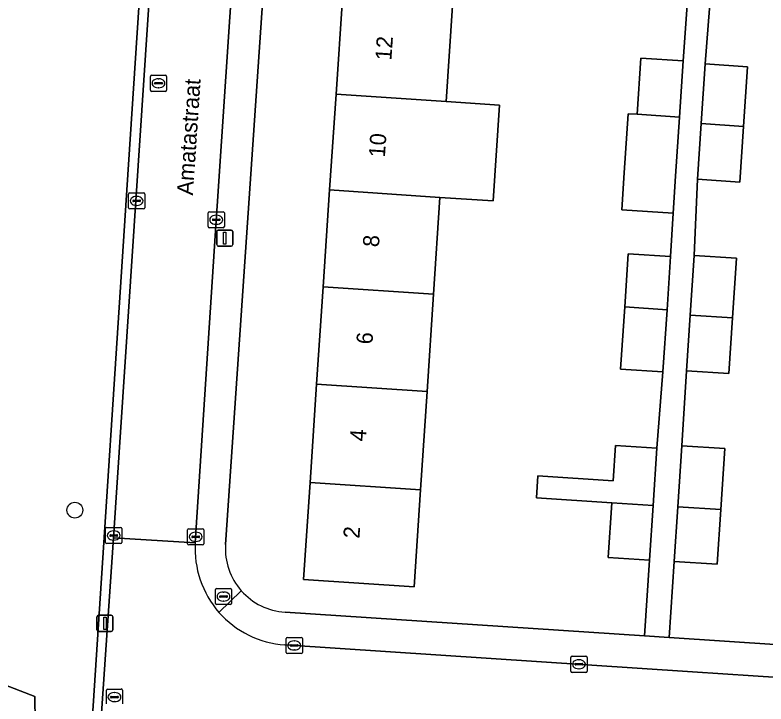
# Model space of a CAD drawing. Extents: x 161848 to 162726, y 385382 to 386521.
# Drawn here: x 161938.67 to 161985.14, y 385769.85 to 385812.47 of the extents above; entities that cross this region are included whole.
import ezdxf

# ---------------------------------------------------------------- set-up
doc = ezdxf.new("R2010")
doc.units = 0
for name, color, linetype in [('IMGEO_Berm_groen', 7, 'Continuous'), ('IMGEO_Boom', 7, 'Continuous'), ('IMGEO_Brandkraan', 7, 'Continuous'), ('IMGEO_Erf', 7, 'Continuous'), ('IMGEO_Kolk', 7, 'Continuous'), ('IMGEO_Lichtmast', 7, 'Continuous'), ('IMGEO_Openbare_ruimte_label', 7, 'Continuous'), ('IMGEO_Pand', 7, 'Continuous'), ('IMGEO_Pand_nummerreeks', 7, 'Continuous'), ('IMGEO_Rijbaan_lokaal_open', 7, 'Continuous'), ('IMGEO_Rioolput', 7, 'Continuous'), ('IMGEO_Verkeerseiland_open', 7, 'Continuous'), ('IMGEO_Voetpad_open', 7, 'Continuous')]:
    doc.layers.add(name, color=color, linetype=linetype)

msp = doc.modelspace()

# ---------------------------------------------------------------- linework, layer by layer
at = {"layer": 'IMGEO_Berm_groen'}
msp.add_lwpolyline([(161931.525, 385832.871), (161933.818, 385847.74), (161934.084, 385852.209), (161933.585, 385852.239), (161932.486, 385852.287), (161932.221, 385847.839), (161924.449, 385848.323), (161920.862, 385793.562), (161908.293, 385794.092), (161907.152, 385778.61), (161908.997, 385778.473), (161908.591, 385768.327), (161908.991, 385768.299), (161939.908, 385768.742), (161939.891, 385770.318), (161927.656, 385775.034)], close=True, dxfattribs=at)
msp.add_lwpolyline([(161947.7, 385838.093), (161943.41, 385838.314), (161943.973, 385847.108), (161933.818, 385847.74), (161931.525, 385832.871), (161927.656, 385775.034), (161939.891, 385770.318), (161939.908, 385768.742), (161943.443, 385768.793), (161945.684, 385803.221), (161947.829, 385835.828)], dxfattribs=at)
at = {"layer": 'IMGEO_Boom'}
msp.add_circle((161942.377, 385781.84), 0.489, dxfattribs=at)
at = {"layer": 'IMGEO_Brandkraan'}
for p, q in [((161951.072, 385776.073), (161951.072, 385776.925)), ((161951.147, 385776.999), (161951.999, 385776.999)), ((161951.56, 385776.779), (161951.585, 385776.779)), ((161952.073, 385776.925), (161952.073, 385776.073)), ((161951.331, 385776.493), (161951.331, 385776.505)), ((161951.769, 385776.456), (161951.371, 385776.456)), ((161951.374, 385776.542), (161951.772, 385776.542)), ((161951.583, 385776.219), (161951.558, 385776.219)), ((161951.815, 385776.505), (161951.815, 385776.493)), ((161951.999, 385775.999), (161951.147, 385775.999))]:
    msp.add_line(p, q, dxfattribs=at)
for points in [[(161951.072, 385776.073), (161951.072, 385776.925)], [(161951.147, 385776.999), (161951.999, 385776.999)], [(161952.073, 385776.925), (161952.073, 385776.073)], [(161951.999, 385775.999), (161951.147, 385775.999)]]:
    msp.add_lwpolyline(points, dxfattribs=at)
for centre, radius, start, end in [((161951.149, 385776.923), 0.0765, 91.552, 178.448), ((161951.149, 385776.923), 0.0765, 91.552, 178.448), ((161951.997, 385776.923), 0.0765, 1.552, 88.448), ((161951.997, 385776.923), 0.0765, 1.552, 88.448), ((161951.371, 385776.502), 0.0403, 85.8775, 175.7526), ((161951.368, 385776.492), 0.0366, 178.938, 274.7102), ((161951.772, 385776.499), 0.043, 264.8664, 352.4533), ((161951.776, 385776.504), 0.0386, 1.7309, 96.639), ((161951.149, 385776.075), 0.0765, 181.552, 268.448), ((161951.149, 385776.075), 0.0765, 181.552, 268.448), ((161951.997, 385776.075), 0.0765, 271.552, 358.448), ((161951.997, 385776.075), 0.0765, 271.552, 358.448)]:
    msp.add_arc(centre, radius, start, end, dxfattribs=at)
for centre, major_axis, ratio, start_param, end_param in [((161951.559, 385776.499), (-0.387, 0.002), 0.722429, 4.712389, 7.853982), ((161951.584, 385776.499), (-0.39, 0.002), 0.717154, 1.570796, 4.712389)]:
    msp.add_ellipse(centre, major_axis=major_axis, ratio=ratio, start_param=start_param, end_param=end_param, dxfattribs=at)
at = {"layer": 'IMGEO_Erf'}
for points in [[(161977.392, 385809.804), (161980.014, 385809.631), (161980.348, 385814.258), (161977.727, 385814.432), (161977.978, 385818.234), (161978.199, 385821.56), (161980.821, 385821.387), (161981.18, 385826.49), (161978.559, 385826.664), (161978.792, 385830.19), (161979.031, 385833.792), (161981.653, 385833.619), (161982.073, 385839.965), (161959.679, 385841.448)], [(161955.683, 385837.954), (161951.696, 385779.71)], [(161981.747, 385814.218), (161981.378, 385809.448), (161983.998, 385809.274), (161983.753, 385805.579), (161983.525, 385802.138), (161980.905, 385802.312), (161980.693, 385797.6), (161983.313, 385797.426), (161983.069, 385793.741), (161982.84, 385790.29), (161980.22, 385790.464), (161979.94, 385785.823), (161982.587, 385785.648), (161982.339, 385781.883), (161982.116, 385778.499), (161979.469, 385778.674), (161979.158, 385773.957), (162000, 385772.581), (162004.679, 385772.273)], [(161965.751, 385813.03), (161965.359, 385807.121), (161968.654, 385806.9), (161968.257, 385800.972), (161964.966, 385801.192), (161964.57, 385795.208), (161964.17, 385789.179), (161963.767, 385783.092), (161963.37, 385777.097), (161956.525, 385777.555), (161956.926, 385783.55), (161957.334, 385789.637), (161957.737, 385795.665), (161958.138, 385801.649), (161958.535, 385807.578), (161958.93, 385813.487)], [(161955.379, 385775.527), (161977.618, 385774.059), (161977.928, 385778.75), (161975.378, 385778.918), (161975.601, 385782.3), (161970.933, 385782.613), (161971.023, 385783.969), (161975.691, 385783.656), (161975.835, 385785.839), (161978.385, 385785.671), (161978.764, 385790.4), (161976.143, 385790.574), (161976.397, 385794.417), (161976.615, 385797.702), (161979.237, 385797.529), (161979.389, 385800.205), (161976.217, 385800.415), (161976.369, 385802.713), (161976.612, 385806.368), (161977.162, 385806.331), (161977.392, 385809.804)]]:
    msp.add_lwpolyline(points, dxfattribs=at)
for centre, radius, start, end in [((161955.636, 385779.468), 3.948, 176.479, 221.3765), ((161955.638, 385779.468), 3.949, 221.3634, 266.2374)]:
    msp.add_arc(centre, radius, start, end, dxfattribs=at)
at = {"layer": 'IMGEO_Kolk'}
for p, q in [((161945.699, 385800.546), (161945.699, 385801.398)), ((161945.774, 385801.472), (161946.626, 385801.472)), ((161946.7, 385801.398), (161946.7, 385800.546)), ((161945.958, 385800.966), (161945.958, 385800.978)), ((161946.396, 385800.929), (161945.998, 385800.929)), ((161946.001, 385801.015), (161946.399, 385801.015)), ((161946.187, 385801.252), (161946.212, 385801.252)), ((161946.442, 385800.978), (161946.442, 385800.966)), ((161946.626, 385800.472), (161945.774, 385800.472)), ((161946.21, 385800.692), (161946.185, 385800.692)), ((161950.623, 385799.379), (161950.623, 385800.231)), ((161950.698, 385800.305), (161951.55, 385800.305)), ((161951.111, 385800.085), (161951.136, 385800.085)), ((161951.624, 385800.231), (161951.624, 385799.379)), ((161950.882, 385799.799), (161950.882, 385799.811)), ((161951.32, 385799.762), (161950.922, 385799.762)), ((161950.925, 385799.848), (161951.323, 385799.848)), ((161951.134, 385799.525), (161951.109, 385799.525)), ((161951.366, 385799.811), (161951.366, 385799.799)), ((161951.55, 385799.305), (161950.698, 385799.305)), ((161944.277, 385779.848), (161944.277, 385780.7)), ((161944.352, 385780.774), (161945.204, 385780.774)), ((161944.765, 385780.554), (161944.79, 385780.554)), ((161945.278, 385780.7), (161945.278, 385779.848)), ((161949.351, 385779.766), (161949.351, 385780.618)), ((161949.426, 385780.692), (161950.278, 385780.692)), ((161949.839, 385780.472), (161949.864, 385780.472)), ((161950.352, 385780.618), (161950.352, 385779.766)), ((161944.536, 385780.268), (161944.536, 385780.28)), ((161944.974, 385780.231), (161944.576, 385780.231)), ((161944.579, 385780.317), (161944.977, 385780.317)), ((161944.788, 385779.994), (161944.763, 385779.994)), ((161945.02, 385780.28), (161945.02, 385780.268)), ((161949.61, 385780.186), (161949.61, 385780.198)), ((161950.048, 385780.149), (161949.65, 385780.149)), ((161949.653, 385780.235), (161950.051, 385780.235)), ((161949.862, 385779.912), (161949.837, 385779.912)), ((161950.094, 385780.198), (161950.094, 385780.186)), ((161945.204, 385779.774), (161944.352, 385779.774)), ((161950.278, 385779.692), (161949.426, 385779.692)), ((161955.451, 385773.048), (161955.451, 385773.9)), ((161955.526, 385773.974), (161956.378, 385773.974)), ((161956.452, 385773.9), (161956.452, 385773.048)), ((161955.71, 385773.468), (161955.71, 385773.48)), ((161956.148, 385773.431), (161955.75, 385773.431)), ((161955.753, 385773.517), (161956.151, 385773.517)), ((161955.939, 385773.754), (161955.964, 385773.754)), ((161956.194, 385773.48), (161956.194, 385773.468)), ((161956.378, 385772.974), (161955.526, 385772.974)), ((161955.962, 385773.194), (161955.937, 385773.194)), ((161973.067, 385771.883), (161973.067, 385772.735)), ((161973.142, 385772.809), (161973.994, 385772.809)), ((161973.555, 385772.589), (161973.58, 385772.589)), ((161974.068, 385772.735), (161974.068, 385771.883)), ((161973.326, 385772.303), (161973.326, 385772.315)), ((161973.764, 385772.266), (161973.366, 385772.266)), ((161973.369, 385772.352), (161973.767, 385772.352)), ((161973.578, 385772.029), (161973.553, 385772.029)), ((161973.81, 385772.315), (161973.81, 385772.303)), ((161973.994, 385771.809), (161973.142, 385771.809))]:
    msp.add_line(p, q, dxfattribs=at)
for points in [[(161945.699, 385800.546), (161945.699, 385801.398)], [(161945.774, 385801.472), (161946.626, 385801.472)], [(161946.7, 385801.398), (161946.7, 385800.546)], [(161946.626, 385800.472), (161945.774, 385800.472)], [(161950.623, 385799.379), (161950.623, 385800.231)], [(161950.698, 385800.305), (161951.55, 385800.305)], [(161951.624, 385800.231), (161951.624, 385799.379)], [(161951.55, 385799.305), (161950.698, 385799.305)], [(161944.277, 385779.848), (161944.277, 385780.7)], [(161944.352, 385780.774), (161945.204, 385780.774)], [(161945.278, 385780.7), (161945.278, 385779.848)], [(161949.351, 385779.766), (161949.351, 385780.618)], [(161949.426, 385780.692), (161950.278, 385780.692)], [(161950.352, 385780.618), (161950.352, 385779.766)], [(161945.204, 385779.774), (161944.352, 385779.774)], [(161950.278, 385779.692), (161949.426, 385779.692)], [(161955.451, 385773.048), (161955.451, 385773.9)], [(161955.526, 385773.974), (161956.378, 385773.974)], [(161956.452, 385773.9), (161956.452, 385773.048)], [(161956.378, 385772.974), (161955.526, 385772.974)], [(161973.067, 385771.883), (161973.067, 385772.735)], [(161973.142, 385772.809), (161973.994, 385772.809)], [(161974.068, 385772.735), (161974.068, 385771.883)], [(161973.994, 385771.809), (161973.142, 385771.809)]]:
    msp.add_lwpolyline(points, dxfattribs=at)
for centre, radius, start, end in [((161945.776, 385801.396), 0.0765, 91.552, 178.448), ((161945.776, 385801.396), 0.0765, 91.552, 178.448), ((161946.624, 385801.396), 0.0765, 1.552, 88.448), ((161946.624, 385801.396), 0.0765, 1.552, 88.448), ((161945.998, 385800.975), 0.0403, 85.8775, 175.7526), ((161945.995, 385800.965), 0.0366, 178.938, 274.7102), ((161946.399, 385800.972), 0.043, 264.8664, 352.4533), ((161946.403, 385800.977), 0.0386, 1.7309, 96.639), ((161945.776, 385800.548), 0.0765, 181.552, 268.448), ((161945.776, 385800.548), 0.0765, 181.552, 268.448), ((161946.624, 385800.548), 0.0765, 271.552, 358.448), ((161946.624, 385800.548), 0.0765, 271.552, 358.448), ((161950.7, 385800.229), 0.0765, 91.552, 178.448), ((161950.7, 385800.229), 0.0765, 91.552, 178.448), ((161951.548, 385800.229), 0.0765, 1.552, 88.448), ((161951.548, 385800.229), 0.0765, 1.552, 88.448), ((161950.922, 385799.808), 0.0403, 85.8775, 175.7526), ((161950.919, 385799.798), 0.0366, 178.938, 274.7102), ((161951.323, 385799.805), 0.043, 264.8664, 352.4533), ((161951.327, 385799.81), 0.0386, 1.7309, 96.639), ((161950.7, 385799.381), 0.0765, 181.552, 268.448), ((161950.7, 385799.381), 0.0765, 181.552, 268.448), ((161951.548, 385799.381), 0.0765, 271.552, 358.448), ((161951.548, 385799.381), 0.0765, 271.552, 358.448), ((161944.354, 385780.698), 0.0765, 91.552, 178.448), ((161944.354, 385780.698), 0.0765, 91.552, 178.448), ((161945.202, 385780.698), 0.0765, 1.552, 88.448), ((161945.202, 385780.698), 0.0765, 1.552, 88.448), ((161949.428, 385780.616), 0.0765, 91.552, 178.448), ((161949.428, 385780.616), 0.0765, 91.552, 178.448), ((161950.276, 385780.616), 0.0765, 1.552, 88.448), ((161950.276, 385780.616), 0.0765, 1.552, 88.448), ((161944.576, 385780.277), 0.0403, 85.8775, 175.7526), ((161944.573, 385780.267), 0.0366, 178.938, 274.7102), ((161944.977, 385780.274), 0.043, 264.8664, 352.4533), ((161944.981, 385780.279), 0.0386, 1.7309, 96.639), ((161949.65, 385780.195), 0.0403, 85.8775, 175.7526), ((161949.647, 385780.185), 0.0366, 178.938, 274.7102), ((161950.051, 385780.192), 0.043, 264.8664, 352.4533), ((161950.055, 385780.197), 0.0386, 1.7309, 96.639), ((161944.354, 385779.85), 0.0765, 181.552, 268.448), ((161944.354, 385779.85), 0.0765, 181.552, 268.448), ((161945.202, 385779.85), 0.0765, 271.552, 358.448), ((161945.202, 385779.85), 0.0765, 271.552, 358.448), ((161949.428, 385779.768), 0.0765, 181.552, 268.448), ((161949.428, 385779.768), 0.0765, 181.552, 268.448), ((161950.276, 385779.768), 0.0765, 271.552, 358.448), ((161950.276, 385779.768), 0.0765, 271.552, 358.448), ((161955.528, 385773.898), 0.0765, 91.552, 178.448), ((161955.528, 385773.898), 0.0765, 91.552, 178.448), ((161956.376, 385773.898), 0.0765, 1.552, 88.448), ((161956.376, 385773.898), 0.0765, 1.552, 88.448), ((161955.75, 385773.477), 0.0403, 85.8775, 175.7526), ((161955.747, 385773.467), 0.0366, 178.938, 274.7102), ((161956.151, 385773.474), 0.043, 264.8664, 352.4533), ((161956.155, 385773.479), 0.0386, 1.7309, 96.639), ((161955.528, 385773.05), 0.0765, 181.552, 268.448), ((161955.528, 385773.05), 0.0765, 181.552, 268.448), ((161956.376, 385773.05), 0.0765, 271.552, 358.448), ((161956.376, 385773.05), 0.0765, 271.552, 358.448), ((161973.144, 385772.733), 0.0765, 91.552, 178.448), ((161973.144, 385772.733), 0.0765, 91.552, 178.448), ((161973.992, 385772.733), 0.0765, 1.552, 88.448), ((161973.992, 385772.733), 0.0765, 1.552, 88.448), ((161973.366, 385772.312), 0.0403, 85.8775, 175.7526), ((161973.363, 385772.302), 0.0366, 178.938, 274.7102), ((161973.767, 385772.309), 0.043, 264.8664, 352.4533), ((161973.771, 385772.314), 0.0386, 1.7309, 96.639), ((161973.144, 385771.885), 0.0765, 181.552, 268.448), ((161973.144, 385771.885), 0.0765, 181.552, 268.448), ((161973.992, 385771.885), 0.0765, 271.552, 358.448), ((161973.992, 385771.885), 0.0765, 271.552, 358.448)]:
    msp.add_arc(centre, radius, start, end, dxfattribs=at)
for centre, major_axis, ratio, start_param, end_param in [((161946.186, 385800.972), (-0.387, 0.002), 0.722429, 4.712389, 7.853982), ((161946.211, 385800.972), (-0.39, 0.002), 0.717154, 1.570796, 4.712389), ((161951.11, 385799.805), (-0.387, 0.002), 0.722429, 4.712389, 7.853982), ((161951.135, 385799.805), (-0.39, 0.002), 0.717154, 1.570796, 4.712389), ((161944.764, 385780.274), (-0.387, 0.002), 0.722429, 4.712389, 7.853982), ((161944.789, 385780.274), (-0.39, 0.002), 0.717154, 1.570796, 4.712389), ((161949.838, 385780.192), (-0.387, 0.002), 0.722429, 4.712389, 7.853982), ((161949.863, 385780.192), (-0.39, 0.002), 0.717154, 1.570796, 4.712389), ((161955.938, 385773.474), (-0.387, 0.002), 0.722429, 4.712389, 7.853982), ((161955.963, 385773.474), (-0.39, 0.002), 0.717154, 1.570796, 4.712389), ((161973.554, 385772.309), (-0.387, 0.002), 0.722429, 4.712389, 7.853982), ((161973.579, 385772.309), (-0.39, 0.002), 0.717154, 1.570796, 4.712389)]:
    msp.add_ellipse(centre, major_axis=major_axis, ratio=ratio, start_param=start_param, end_param=end_param, dxfattribs=at)
at = {"layer": 'IMGEO_Lichtmast'}
for p, q in [((161951.15, 385798.271), (161951.15, 385799.071)), ((161951.15, 385799.071), (161951.15, 385798.271)), ((161951.25, 385799.171), (161952.04, 385799.171)), ((161952.04, 385799.171), (161951.25, 385799.171)), ((161952.14, 385799.071), (161952.14, 385798.271)), ((161952.14, 385798.271), (161952.14, 385799.071)), ((161952.04, 385798.171), (161951.25, 385798.171)), ((161951.25, 385798.171), (161952.04, 385798.171)), ((161943.74, 385774.443), (161943.74, 385775.243)), ((161943.74, 385775.243), (161943.74, 385774.443)), ((161943.84, 385775.343), (161944.63, 385775.343)), ((161944.63, 385775.343), (161943.84, 385775.343)), ((161944.73, 385775.243), (161944.73, 385774.443)), ((161944.73, 385774.443), (161944.73, 385775.243)), ((161944.63, 385774.343), (161943.84, 385774.343)), ((161943.84, 385774.343), (161944.63, 385774.343))]:
    msp.add_line(p, q, dxfattribs=at)
for points in [[(161951.57, 385799.046), (161951.72, 385799.046), (161951.72, 385798.296), (161951.57, 385798.296), (161951.57, 385799.046)], [(161944.16, 385775.218), (161944.31, 385775.218), (161944.31, 385774.468), (161944.16, 385774.468), (161944.16, 385775.218)]]:
    msp.add_lwpolyline(points, dxfattribs=at)
for centre, start, end in [((161951.25, 385799.071), 90, 180), ((161951.25, 385799.071), 90, 180), ((161952.04, 385799.071), 0, 90), ((161952.04, 385799.071), 360, 90), ((161951.25, 385798.271), 180, 270), ((161951.25, 385798.271), 180, 270), ((161952.04, 385798.271), 270, 0), ((161952.04, 385798.271), 270, 0), ((161943.84, 385775.243), 90, 180), ((161943.84, 385775.243), 90, 180), ((161944.63, 385775.243), 0, 90), ((161944.63, 385775.243), 360, 90), ((161943.84, 385774.443), 180, 270), ((161943.84, 385774.443), 180, 270), ((161944.63, 385774.443), 270, 0), ((161944.63, 385774.443), 270, 0)]:
    msp.add_arc(centre, 0.1, start, end, dxfattribs=at)
at = {"layer": 'IMGEO_Pand'}
for points in [[(161965.359, 385807.121), (161965.751, 385813.03), (161958.93, 385813.487), (161958.535, 385807.578)], [(161980.014, 385809.631), (161977.392, 385809.804), (161977.162, 385806.331), (161979.783, 385806.155)], [(161983.998, 385809.274), (161981.378, 385809.448), (161981.133, 385805.752), (161983.753, 385805.579)], [(161968.654, 385806.9), (161965.359, 385807.121), (161958.535, 385807.578), (161958.138, 385801.649), (161964.966, 385801.192), (161968.257, 385800.972)], [(161979.783, 385806.155), (161977.162, 385806.331), (161976.612, 385806.368), (161976.369, 385802.713), (161976.217, 385800.415), (161979.389, 385800.205), (161979.541, 385802.502)], [(161980.905, 385802.312), (161983.525, 385802.138), (161983.753, 385805.579), (161981.133, 385805.752)], [(161958.138, 385801.649), (161957.737, 385795.665), (161964.57, 385795.208), (161964.966, 385801.192)], [(161979.237, 385797.529), (161976.615, 385797.702), (161976.397, 385794.417), (161979.019, 385794.242)], [(161983.313, 385797.426), (161980.693, 385797.6), (161980.449, 385793.914), (161983.069, 385793.741)], [(161964.17, 385789.179), (161964.57, 385795.208), (161957.737, 385795.665), (161957.334, 385789.637)], [(161976.143, 385790.574), (161978.764, 385790.4), (161979.019, 385794.242), (161976.397, 385794.417)], [(161980.22, 385790.464), (161982.84, 385790.29), (161983.069, 385793.741), (161980.449, 385793.914)], [(161963.767, 385783.092), (161964.17, 385789.179), (161957.334, 385789.637), (161956.926, 385783.55)], [(161978.385, 385785.671), (161975.835, 385785.839), (161975.691, 385783.656), (161971.023, 385783.969), (161970.933, 385782.613), (161975.601, 385782.3), (161978.151, 385782.129)], [(161982.339, 385781.883), (161982.587, 385785.648), (161979.94, 385785.823), (161979.692, 385782.058)], [(161956.926, 385783.55), (161956.525, 385777.555), (161963.37, 385777.097), (161963.767, 385783.092)], [(161975.601, 385782.3), (161975.378, 385778.918), (161977.928, 385778.75), (161978.151, 385782.129)], [(161979.692, 385782.058), (161979.469, 385778.674), (161982.116, 385778.499), (161982.339, 385781.883)]]:
    msp.add_lwpolyline(points, close=True, dxfattribs=at)
at = {"layer": 'IMGEO_Rijbaan_lokaal_open'}
msp.add_lwpolyline([(161953.684, 385837.905), (161948.626, 385838.255), (161948.566, 385837.444), (161948.494, 385836.471), (161944.769, 385780.141), (161949.827, 385779.824), (161951.056, 385798.814)], close=True, dxfattribs=at)
for points in [[(161949.827, 385779.824), (161944.769, 385780.141), (161944.03, 385769.276), (162000, 385765.501), (162001.676, 385765.394), (162004.668, 385765.161), (162006.857, 385764.99), (162007.207, 385770.068), (162005.411, 385770.176), (162000, 385770.558), (161984.346, 385771.594)], [(161984.346, 385771.594), (161980.601, 385771.842), (161955.369, 385773.511)]]:
    msp.add_lwpolyline(points, dxfattribs=at)
for centre, radius, start, end in [((161955.76, 385779.443), 5.945, 176.326, 221.2774), ((161955.76, 385779.445), 5.946, 221.286, 266.2265)]:
    msp.add_arc(centre, radius, start, end, dxfattribs=at)
at = {"layer": 'IMGEO_Rioolput'}
for p, q in [((161947.125, 385808.748), (161947.977, 385808.748)), ((161947.05, 385807.822), (161947.05, 385808.674)), ((161947.309, 385808.242), (161947.309, 385808.254)), ((161947.352, 385808.291), (161947.75, 385808.291)), ((161947.538, 385808.528), (161947.563, 385808.528)), ((161947.793, 385808.254), (161947.793, 385808.242)), ((161948.051, 385808.674), (161948.051, 385807.822)), ((161947.747, 385808.205), (161947.349, 385808.205)), ((161947.561, 385807.968), (161947.536, 385807.968)), ((161947.977, 385807.748), (161947.125, 385807.748)), ((161944.322, 385769.854), (161944.322, 385770.706)), ((161944.397, 385770.78), (161945.249, 385770.78)), ((161945.323, 385770.706), (161945.323, 385769.854)), ((161944.581, 385770.274), (161944.581, 385770.286)), ((161945.019, 385770.237), (161944.621, 385770.237)), ((161944.624, 385770.323), (161945.022, 385770.323)), ((161944.81, 385770.56), (161944.835, 385770.56)), ((161945.065, 385770.286), (161945.065, 385770.274)), ((161944.833, 385770), (161944.808, 385770))]:
    msp.add_line(p, q, dxfattribs=at)
for points in [[(161947.125, 385808.748), (161947.977, 385808.748)], [(161947.05, 385807.822), (161947.05, 385808.674)], [(161948.051, 385808.674), (161948.051, 385807.822)], [(161947.977, 385807.748), (161947.125, 385807.748)], [(161944.322, 385769.854), (161944.322, 385770.706)], [(161944.397, 385770.78), (161945.249, 385770.78)], [(161945.323, 385770.706), (161945.323, 385769.854)]]:
    msp.add_lwpolyline(points, dxfattribs=at)
for centre, radius, start, end in [((161947.127, 385808.672), 0.0765, 91.552, 178.448), ((161947.127, 385808.672), 0.0765, 91.552, 178.448), ((161947.975, 385808.672), 0.0765, 1.552, 88.448), ((161947.975, 385808.672), 0.0765, 1.552, 88.448), ((161947.349, 385808.251), 0.0403, 85.8775, 175.7526), ((161947.346, 385808.241), 0.0366, 178.938, 274.7102), ((161947.75, 385808.248), 0.043, 264.8664, 352.4533), ((161947.754, 385808.253), 0.0386, 1.7309, 96.639), ((161947.127, 385807.824), 0.0765, 181.552, 268.448), ((161947.127, 385807.824), 0.0765, 181.552, 268.448), ((161947.975, 385807.824), 0.0765, 271.552, 358.448), ((161947.975, 385807.824), 0.0765, 271.552, 358.448), ((161944.399, 385770.704), 0.0765, 91.552, 178.448), ((161944.399, 385770.704), 0.0765, 91.552, 178.448), ((161945.247, 385770.704), 0.0765, 1.552, 88.448), ((161945.247, 385770.704), 0.0765, 1.552, 88.448), ((161944.621, 385770.283), 0.0403, 85.8775, 175.7526), ((161944.618, 385770.273), 0.0366, 178.938, 274.7102), ((161945.022, 385770.28), 0.043, 264.8664, 352.4533), ((161945.026, 385770.285), 0.0386, 1.7309, 96.639)]:
    msp.add_arc(centre, radius, start, end, dxfattribs=at)
for centre, major_axis, ratio, start_param, end_param in [((161947.537, 385808.248), (-0.387, 0.002), 0.722429, 4.712389, 7.853982), ((161947.562, 385808.248), (-0.39, 0.002), 0.717154, 1.570796, 4.712389), ((161944.809, 385770.28), (-0.387, 0.002), 0.722429, 4.712389, 7.853982), ((161944.834, 385770.28), (-0.39, 0.002), 0.717154, 1.570796, 4.712389)]:
    msp.add_ellipse(centre, major_axis=major_axis, ratio=ratio, start_param=start_param, end_param=end_param, dxfattribs=at)
at = {"layer": 'IMGEO_Verkeerseiland_open'}
msp.add_lwpolyline([(161944.769, 385780.141), (161948.494, 385836.471), (161948.121, 385836.496), (161947.874, 385836.512), (161947.829, 385835.828), (161945.684, 385803.221), (161943.443, 385768.793), (161943.992, 385768.753), (161944.03, 385769.276)], close=True, dxfattribs=at)
at = {"layer": 'IMGEO_Voetpad_open'}
for points in [[(161953.684, 385837.905), (161951.056, 385798.814), (161949.827, 385779.824)], [(161951.696, 385779.71), (161955.683, 385837.954)], [(161980.348, 385814.258), (161980.014, 385809.631), (161979.783, 385806.155), (161979.541, 385802.502), (161979.389, 385800.205), (161979.237, 385797.529), (161979.019, 385794.242), (161978.764, 385790.4), (161978.385, 385785.671), (161978.151, 385782.129), (161977.928, 385778.75), (161977.618, 385774.059), (161979.158, 385773.957), (161979.469, 385778.674), (161979.692, 385782.058), (161979.94, 385785.823), (161980.22, 385790.464), (161980.449, 385793.914), (161980.693, 385797.6), (161980.905, 385802.312), (161981.133, 385805.752), (161981.378, 385809.448), (161981.747, 385814.218)], [(161952.674, 385776.858), (161951.292, 385775.521)], [(161951.292, 385775.521), (161952.674, 385776.858)], [(162004.679, 385772.273), (162000, 385772.581), (161979.158, 385773.957), (161977.618, 385774.059), (161955.379, 385775.527)], [(161955.369, 385773.511), (161980.601, 385771.842), (161984.346, 385771.594), (162000, 385770.558), (162005.411, 385770.176), (162007.207, 385770.068), (162008.172, 385770.043), (162008.506, 385774.751)]]:
    msp.add_lwpolyline(points, dxfattribs=at)
for centre, radius, start, end in [((161955.76, 385779.443), 5.945, 176.326, 221.2774), ((161955.636, 385779.468), 3.948, 176.479, 221.3765), ((161955.638, 385779.468), 3.949, 221.3634, 266.2374), ((161955.76, 385779.445), 5.946, 221.286, 266.2265)]:
    msp.add_arc(centre, radius, start, end, dxfattribs=at)

# ---------------------------------------------------------------- texts
at = {"layer": 'IMGEO_Openbare_ruimte_label'}
msp.add_text('Amatastraat', height=1, rotation=86.1593, dxfattribs=at).set_placement((161949.678, 385801.296))
at = {"layer": 'IMGEO_Pand_nummerreeks'}
for s, rotation, p in [('12', 86.1705, (161961.96, 385809.639)), ('10', 86.1729, (161961.558, 385803.638)), ('8', 86.1705, (161961.187, 385798.091)), ('6', 86.1705, (161960.785, 385792.079)), ('4', 86.1705, (161960.383, 385786.072)), ('2', 86.1705, (161959.98, 385780.063))]:
    msp.add_text(s, height=1, rotation=rotation, dxfattribs=at).set_placement(p)

doc.saveas('drawing.dxf')
